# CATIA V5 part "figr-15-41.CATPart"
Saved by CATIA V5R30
Part number: Part1
Bounding box of the stored display mesh (mm): x -55.204 to 69.266, y -33.79 to 44.107, z 0 to 118.408
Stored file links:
  D:\PROJECTS\CATIA V56R 2020\Resources\Parts File\c15_catia_v5_6r2020_prt\figr-15-41.CATPart
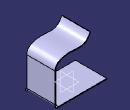
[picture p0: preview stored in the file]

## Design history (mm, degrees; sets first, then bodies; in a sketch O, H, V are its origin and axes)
SheetMetalParameters1: Thickness 2, BendRadius 4, KFactor 0.400515 {= log(min(100,max(20*SheetMetalParameters1.BendRadius,SheetMetalParameters1.Thickness)/SheetMetalParameters1.Thickness))/log(100)/2}, ReliefRadialLength 1, ReliefAxialLength 2, MinimumBendRadius 0
Body1 (main body)
  Sketch1 on xy-plane, origin (0, 0, 0), H (1, 0, 0), V (0, 1, 0)
    line L1 (-55.2037, 44.1067) -> (69.266, 44.1067)
    line L2 (69.266, 44.1067) -> (69.266, -33.7896)
    line L3 (69.266, -33.7896) -> (-55.2037, -33.7896)
    line L4 (-55.2037, -33.7896) -> (-55.2037, 44.1067)
    horizontal: L1 H, L3 H
    vertical: L2 V, L4 V
  Wall1: Thickness 2, Profile Sketch1, OffsetValue 0
  d_NewWallOnEdge1: NewWallOnEdge_Length 77.8964, NewWallOnEdge_HeightLimitOffset 0, NewWallOnEdge_WidthOffset1 -4, NewWallOnEdge_WidthOffset2 -4, NewWallOnEdge_Angle 90, NewWallOnEdge_BendRadiusValue 4 {= SheetMetalParameters1.BendRadius}, NewWallOnEdge_BendTable SheetMetalParameters1, NewWallOnEdge_Edge edge [face of Wall1 | face of Wall1], NewWallOnEdge_GapValue 0, KFacteur 0.400515 {= log(min(100,max(20*d_NewWallOnEdge1.Radius,SheetMetalParameters1.Thickness)/SheetMetalParameters1.Thickness))/log(100)/2}
  Sketch2 on face of d_NewWallOnEdge1, origin (0, 40.1067, 0), H (-1, 0, 0), V (0, 0, 1)
    spline S1 through (-69.266, 77.8964) (-67.9767, 84.9607) (-48.7678, 98.5965) (6.1586, 103.3856) (17.3621, 118.4076)
    reference projected line E1 (-69.266, 6) -> (-69.266, 77.8964) from edge [face of d_NewWallOnEdge1 | face of d_NewWallOnEdge1]
    reference projected line E2 (-69.266, 6) -> (-69.266, 77.8964) from edge [face of d_NewWallOnEdge1 | face of d_NewWallOnEdge1]
    reference projected point E3 (-69.266, 77.8964) from vertex [face of d_NewWallOnEdge1 | face of d_NewWallOnEdge1 | face of d_NewWallOnEdge1]
    point P1 (-69.266, 77.8964)
    coincidence: P1 E1, P1 E3
    tangency: S1 E2
  Flange1: Guide edge [face of d_NewWallOnEdge1 | face of d_NewWallOnEdge1], KFacteur 0.400515 {= SheetMetalParameters1.KFactor}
